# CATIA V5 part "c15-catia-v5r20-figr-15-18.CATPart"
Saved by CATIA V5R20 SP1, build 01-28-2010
Part number: Part1
Bounding box of the stored display mesh (mm): x -46.56 to 46.56, y -38.965 to 25.965, z 0 to 40
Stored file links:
  D:\v5_r20\psrt_files_downloaded\c15\c15-catia-v5r20-figr-15-18.CATPart
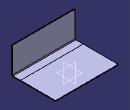
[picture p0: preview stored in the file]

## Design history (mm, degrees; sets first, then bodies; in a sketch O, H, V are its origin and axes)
SheetMetalParameters1: Thickness 1, BendRadius 1, KFactor 0.325257 {= log(min(100,max(20*SheetMetalParameters1.BendRadius,SheetMetalParameters1.Thickness)/SheetMetalParameters1.Thickness))/log(100)/2}, ReliefRadialLength 1, ReliefAxialLength 2, MinimumBendRadius 0
Body1 (main body)
  Sketch1 on xy-plane, origin (0, 0, 0), H (1, 0, 0), V (0, 1, 0)
    line L1 (-46.5596, 25.9646) -> (46.5596, 25.9646)
    line L2 (46.5596, 25.9646) -> (46.5596, -25.9646)
    line L3 (46.5596, -25.9646) -> (-46.5596, -25.9646)
    line L4 (-46.5596, -25.9646) -> (-46.5596, 25.9646)
    horizontal: L1 H, L3 H
    vertical: L2 V, L4 V
    symmetry: L1 L3 H, L4 L2 V
  Wall1: Thickness 1, Profile Sketch1
  d_NewWallOnEdge1: NewWallOnEdge_Edge edge [face of Wall1 | face of Wall1], NewWallOnEdge_Length 40, NewWallOnEdge_HeightLimitOffset 0, NewWallOnEdge_WidthOffset1 0, NewWallOnEdge_WidthOffset2 0, NewWallOnEdge_Angle 90, NewWallOnEdge_BendRadiusValue 1 {= SheetMetalParameters1.BendRadius}, NewWallOnEdge_BendTable SheetMetalParameters1, KFacteur 0.325257 {= log(min(100,max(20*d_NewWallOnEdge1.Radius,SheetMetalParameters1.Thickness)/SheetMetalParameters1.Thickness))/log(100)/2}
